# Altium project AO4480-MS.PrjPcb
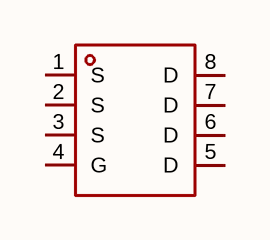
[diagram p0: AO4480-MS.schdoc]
1 sheet, 1 parts. Net scope: global (net labels, ports and power ports of the same name join across sheets).

## Sheet AO4480-MS.schdoc
size 127 x 101 mm

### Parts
Q?  ao4480-ms  [SOP-8_L5.0-W4.0-P1.27-LS6.0-BL]  (value not drawn)

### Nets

Not connected (* = marked no-connect by the designer): Q? 1(S) 2(S) 3(S) 4(G) 5(D) 6(D) 7(D) 8(D)

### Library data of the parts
Q? = ao4480-ms: 数量:1个N沟道;漏源电压(Vdss):40V;连续漏极电流(Id):14A;导通电阻(RDS(on)):13mΩ@10V;耗散功率(Pd):3.1W;阈值电压(Vgs(th)):3V;; Manufacturer: MSKSEMI(美森科); AddInBom: yes; ModelId: a3315c1c78f949e6bb82c6eaca1c53c7; ModelName: SOP-8_L5.0-W4.0-H1.8-LS6.2-P1.27; ModelTransform: 244.094,196.85,0,90,0,0,0,0,0; Number: 1个N沟道; Drain to Source Voltage: 40V; Current - Continuous Drain(Id): 14A; Pd - Power Dissipation: 3.1W; Gate Threshold Voltage (Vgs(th)): 3V; Gate Charge(Qg): 22nC@10V; Input Capacitance(Ciss): 1.6nF; Reverse Transfer Capacitance (Crss@Vds): 100pF; Type: N沟道; Output Capacitance(Coss): 320pF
